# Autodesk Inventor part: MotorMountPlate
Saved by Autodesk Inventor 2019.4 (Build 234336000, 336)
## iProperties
Created: 2020-04
Part Number: MotorMountPlate
Material: Generic
Document SubType Name: Modeling
Designer: Administrator
Density: 1 g/cm^3
Appearance: Default
Title: MotorMountPlate
Author: Administrator
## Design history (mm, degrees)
feature "MotorMountPlate"
body "Solid1"
